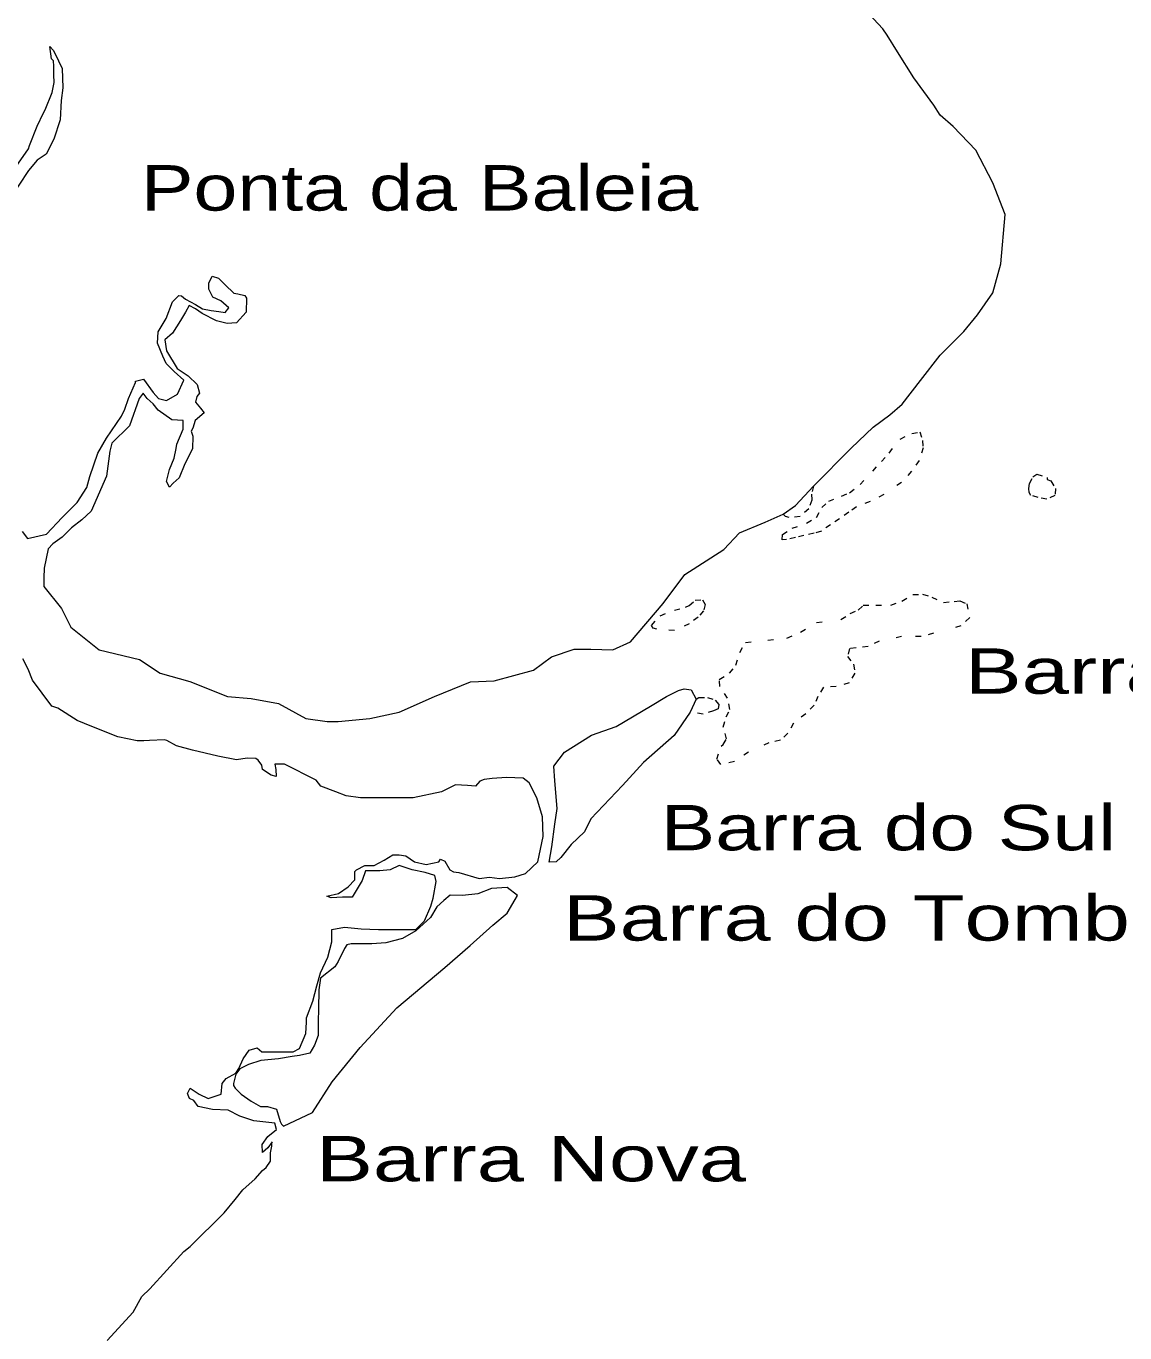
# Model space of a CAD drawing. Extents: x 47169 to 972804, y 7447977 to 9608469.
# Drawn here: x 471352 to 487096, y 8028731 to 8047454 of the extents above; entities that cross this region are included whole.
import ezdxf

# ---------------------------------------------------------------- set-up
doc = ezdxf.new("R2010")
doc.units = 0
doc.header["$LTSCALE"] = 270
doc.linetypes.add('DOTTED', pattern=[1.5, 0.3, -1.2])
doc.layers.add('1', color=7, linetype='Continuous', lineweight=13)
doc.layers.add('3', color=7, linetype='Continuous')

msp = doc.modelspace()

# ---------------------------------------------------------------- linework, layer by layer
at = {"layer": '1'}
for points in [[(475668, 8037489.3), (475821.7, 8037488.3), (476275.4, 8037535.3), (476698.3, 8037626.6), (477205.9, 8037849.5), (477720.9, 8038058.1), (478060.1, 8038072.9), (478620.8, 8038226.2), (478882.5, 8038418.9), (479205.7, 8038526.6), (479444.3, 8038526.9), (479759.2, 8038518.3), (480013.5, 8038633.6), (480482.6, 8039179.5), (480789.7, 8039594.7), (481351.3, 8039955.9), (481574.8, 8040194), (481943.7, 8040348.1), (482198, 8040463.4), (482375, 8040586.4), (482635.6, 8040863.2), (483174.9, 8041409.1), (483489.5, 8041709.2), (483728, 8041885.3), (483904.9, 8042039.2), (484166.6, 8042378), (484451.6, 8042738.8), (484789.6, 8043077.6), (484982.4, 8043315.6), (485205.9, 8043631.1), (485321.2, 8044046.1), (485382.2, 8044753.1), (485205.8, 8045207.7), (484959.4, 8045676.6), (484635.7, 8046014.9), (484451, 8046176.3), (484358.6, 8046323.3), (484074.1, 8046714.8), (483836.2, 8047084.1), (483689.6, 8047322.9), (483628, 8047415.8), (483289.4, 8047777.3)], [(471209.1, 8045441.4), (471385.9, 8045695), (471401.7, 8045741.5), (471508.4, 8046018.2), (471601.5, 8046209.7), (471623.7, 8046256.2), (471724.1, 8046502), (471754.7, 8046648), (471747.1, 8046756.5), (471746.9, 8046879.3), (471746.8, 8046955.6), (471716, 8046986.5), (471692.4, 8047163.5), (471746.6, 8047102.8), (471815.8, 8046955.7), (471870, 8046848.5), (471877.8, 8046571.9), (471854.8, 8046387.1), (471839.2, 8046110.5), (471747.3, 8045833.8), (471639.5, 8045617.9), (471509.1, 8045533.6), (471386.3, 8045387.4), (471109, 8044964.4)], [(473234, 8042910.6), (473242.2, 8043072.2), (473357.6, 8043264.8), (473449.5, 8043502.8), (473541.7, 8043595.9), (473579.9, 8043588.2), (473634, 8043541.8), (473780.5, 8043464.5), (473880.2, 8043402.7), (474003.3, 8043379.6), (474111.5, 8043364.3), (474203.7, 8043348.9), (474256.7, 8043418.7), (474142, 8043518.1), (474026.4, 8043572.2), (473972.1, 8043687.1), (473972, 8043772.3), (474018.5, 8043872), (474110.8, 8043841.1), (474203.2, 8043749.4), (474326.4, 8043625.6), (474387.9, 8043618), (474487.6, 8043594.9), (474511, 8043557.3), (474503.8, 8043357), (474365.1, 8043203.1), (474234.7, 8043195.2), (474079.8, 8043233.7), (473872.9, 8043334.1), (473780.5, 8043402.6), (473688.2, 8043448.9), (473634.2, 8043357), (473564.4, 8043234.1), (473449.1, 8043056.9), (473342.1, 8042957.2), (473364.6, 8042803.5), (473518.7, 8042549.2), (473672.6, 8042442.1), (473804.2, 8042318.4), (473835.1, 8042195.6), (473796, 8042149.1), (473781.2, 8042065), (473850.3, 8041979.9), (473904.4, 8041911.4), (473773.1, 8041803.9), (473742.5, 8041695.4), (473719.2, 8041650), (473742.6, 8041580.3), (473735.5, 8041395.6), (473627.6, 8041180.8), (473543, 8040980.4), (473458.3, 8040904), (473404.3, 8040849.7), (473366, 8040927.1), (473405, 8041103), (473473.7, 8041264.7), (473504.3, 8041403), (473511.6, 8041465), (473604.7, 8041680.8), (473604.5, 8041803.6), (473442.2, 8041811.2), (473242.7, 8041949.2), (473173.6, 8042042), (473088.7, 8042118.3), (473027.1, 8042195.6), (472973.1, 8042119.2), (472834.8, 8041726.3), (472580.6, 8041480.3), (472550, 8041365.2), (472504.9, 8041003.4), (472281.9, 8040504.1), (472150.5, 8040380), (472004.4, 8040264.7), (471866.7, 8040134), (471735.4, 8040034.2), (471666.6, 8039965.5), (471612.9, 8039687.8), (471605.7, 8039549.5), (471605.8, 8039426.7), (471859.7, 8039111.7), (471990.5, 8038841.9), (472398.1, 8038519.4), (472975, 8038380.8), (473275.3, 8038181), (473698.5, 8038065.4), (474237.4, 8037850.3), (474575.6, 8037819.8), (474967.9, 8037750.6), (475360.5, 8037535.3), (475668, 8037489.3)], [(471297.2, 8040211.7), (471373.7, 8040111.2), (471643, 8040172.4), (471866.3, 8040411.7), (472081.3, 8040626.6), (472219.9, 8040841.4), (472266.3, 8041003), (472381.4, 8041334), (472504.1, 8041549.9), (472719, 8041864.4), (472765.5, 8041965.1), (472819.4, 8042119), (472918.7, 8042349.3), (472918.7, 8042364.8), (473034.2, 8042395.9), (473173.4, 8042203.6), (473249.9, 8042118.5), (473365.5, 8042087.7), (473519.2, 8042179.7), (473611.1, 8042380.1), (473473.1, 8042503.8), (473357.4, 8042618.7), (473311.7, 8042726), (473234, 8042910.6)], [(477306, 8036481.1), (476899, 8036396.5), (476606.4, 8036396.2), (476445.3, 8036396), (476145.3, 8036396.8), (475937.5, 8036427.5), (475791.1, 8036481.5), (475575.8, 8036565.3), (475506.8, 8036650.4), (475052.8, 8036881.1), (474913.9, 8036880.9), (474929.9, 8036804.6), (474937.4, 8036703.9), (474861.1, 8036719.3), (474738, 8036804.4), (474729.5, 8036866.3), (474676.4, 8036934.8), (474645.6, 8036958), (474521.5, 8036965.6), (474367.9, 8036943.3), (474098.5, 8036996), (473738, 8037080.8), (473506.8, 8037142.4), (473367.8, 8037219.7), (473337, 8037227.4), (473121.8, 8037219.3), (473037, 8037211.5), (472944.8, 8037211.4), (472668, 8037272.9), (472291.4, 8037419.6), (472083.5, 8037504.5), (471806.6, 8037681.1), (471721.7, 8037712), (471444.5, 8038081.1), (471382.8, 8038242.5), (471306.2, 8038388.5)], [(474871, 8031405.5), (474870.9, 8031452), (474878.3, 8031466.3), (474817, 8031382.2), (474740.8, 8031313.5), (474732.1, 8031428.5), (474816.8, 8031543.7), (474939.6, 8031643.4), (474917.2, 8031736.3), (474617.2, 8031766.9), (474416.8, 8031836.4), (474248.2, 8031920.2), (474024.6, 8031928.8), (473816.8, 8031973.9), (473755.2, 8032059), (473693.7, 8032089.9), (473662.8, 8032158.5), (473702, 8032236), (473832.4, 8032150.9), (473962.9, 8032090.3), (474148.3, 8032151.3), (474162.9, 8032305.2), (474216.9, 8032373.8), (474355.6, 8032451.4), (474401.1, 8032520.1), (474462.4, 8032658.5), (474547, 8032782.5), (474662.5, 8032812.5), (474731.5, 8032758.4), (474823.7, 8032758.5), (475000.7, 8032758.7), (475177.7, 8032759), (475269.9, 8032805.5), (475361.8, 8033020.3), (475370.1, 8033181.8), (475370, 8033243.8), (475462, 8033481.8), (475515.7, 8033705.3), (475569.6, 8033889), (475677.4, 8034112.7), (475731.2, 8034335.1), (475731, 8034512.1), (475915.4, 8034543.3), (476153.9, 8034520.4), (476399.8, 8034511.8), (476745.4, 8034512.2), (476938.3, 8034512.5), (477061.1, 8034635.4), (477153.1, 8034842.4), (477183.7, 8034958.6), (477230.1, 8035196.5), (477206.7, 8035281.7), (477068.8, 8035326.9), (476884.3, 8035365.4), (476699.8, 8035427.1), (476568.4, 8035366.1), (476422.2, 8035350.5), (476214.4, 8035350.2), (476169, 8035211.9), (476023, 8034973.8), (475884.1, 8034973.7), (475723, 8034965.7), (475661.5, 8034988.9), (475830, 8035027.8), (475968.8, 8035119.8), (476060.8, 8035219.5), (476060.7, 8035343.4), (476084, 8035365.5), (476206.9, 8035427.7), (476338.3, 8035427.8), (476483.5, 8035504.3), (476607.4, 8035580.8), (476699.6, 8035580.9), (476791.9, 8035565.5), (476914.9, 8035481.6), (477083.5, 8035443.1), (477267.9, 8035480.9), (477291.2, 8035519.6), (477352.7, 8035488.7), (477421.8, 8035366), (477475.9, 8035335.1), (477553.3, 8035327.4), (477844.9, 8035242.6), (477991.1, 8035258.2), (478137.4, 8035242.9), (478352.6, 8035265.2), (478506.3, 8035311.9), (478683.1, 8035481.4), (478760.1, 8035842.1), (478752.4, 8036126.4), (478668.4, 8036396.3), (478560, 8036611.9), (478475.1, 8036680.4), (478236.6, 8036689), (478029.9, 8036673.3), (477914.3, 8036657.7), (477852.9, 8036634.4), (477791.5, 8036565.7), (477675.9, 8036573.3), (477506.3, 8036580.9), (477306, 8036481.1)], [(472512.5, 8028620.9), (472888.1, 8029028.6), (473011.8, 8029252.3), (473127.2, 8029359.7), (473610.7, 8029898.1), (473702.8, 8029966.8), (474187.6, 8030452), (474348.4, 8030643.6), (474456.3, 8030782.1), (474633.1, 8030936.1), (474740, 8031059), (474794, 8031097.8), (474855.4, 8031189.7), (474855.2, 8031312.5), (474871, 8031405.5)]]:
    msp.add_lwpolyline(points, dxfattribs=at)
at = {"layer": '1', "linetype": 'DOTTED'}
for points in [[(483482.6, 8041077.4), (483607.7, 8041214.7), (483716.8, 8041337.6), (483874.6, 8041538), (484045.2, 8041618.9), (484159.8, 8041640), (484194.9, 8041518.3), (484205.5, 8041411), (484149.5, 8041228.4), (484037.2, 8041077.9), (483895.2, 8040915.1), (483640.9, 8040744.5), (483446.9, 8040640.4), (483248.7, 8040567.2), (483139.6, 8040487.5), (483007.1, 8040396.6), (482877.8, 8040310.2), (482747.5, 8040218.3), (482643.6, 8040187.2), (482498.4, 8040155), (482376.5, 8040126.1), (482246.1, 8040098.4), (482187.8, 8040092.8), (482189.8, 8040169.1), (482327.6, 8040258.8), (482536.4, 8040332), (482676.3, 8040414), (482752.5, 8040555.7), (482852.1, 8040647.6), (483037.6, 8040718.6), (483152.1, 8040767.4), (483302.5, 8040884.8)], [(485983, 8040957.6), (486033.9, 8040936.7), (486101.9, 8040828.3), (486094.5, 8040730.9), (485977.9, 8040677.7), (485852.8, 8040700.9), (485751, 8040730.7), (485723.4, 8040769.4), (485718, 8040830.2), (485727.5, 8040901), (485779.4, 8040995.1), (485834.5, 8041036.1), (485985.1, 8040987.5)], [(482448.7, 8038772), (482679.7, 8038907.2), (483028.5, 8038952.9), (483161, 8039039.2), (483275.4, 8039088), (483348.5, 8039156.7), (483527.7, 8039159), (483740.8, 8039159.2), (483900.9, 8039215.8), (484056.6, 8039309.9), (484198.7, 8039314.5), (484329.2, 8039271.4), (484496.7, 8039197.4), (484649.4, 8039210.8), (484733.2, 8039220.9), (484830.7, 8039177.8), (484873.3, 8038979.8), (484746.2, 8038860.2), (484176.9, 8038707.1), (483897, 8038706.9), (483575.8, 8038643.5), (483417.9, 8038564.8), (483245.1, 8038547), (483148.7, 8038535.9), (483120.1, 8038421.9), (483207.2, 8038312.4), (483227.4, 8038183), (483145.9, 8038045.7), (482958.3, 8037990.3), (482779.1, 8037982.4), (482698.7, 8037849.5), (482642.6, 8037722.2), (482522.9, 8037602.7), (482350.2, 8037465.3), (482265.5, 8037323.6), (482161.7, 8037221.8), (481994.2, 8037186.2), (481703.9, 8037053.2), (481502.6, 8036915.8), (481306.5, 8036875.8), (481250.2, 8036951), (481311.5, 8037136.9), (481342.3, 8037160.2), (481387.8, 8037241), (481342, 8037411.3), (481385.4, 8037556.3), (481436.2, 8037663.6), (481403.1, 8037822.9), (481292.7, 8037991), (481285.2, 8038092.8), (481430.4, 8038183.6), (481522.5, 8038296.5), (481577.5, 8038479.2), (481662.2, 8038622), (481982.3, 8038654.3), (482254.8, 8038685.5)], [(480855.1, 8038892.2), (480643.1, 8038795.8), (480391.8, 8038813.2), (480337.7, 8038826.5), (480312.2, 8038866.3), (480439.3, 8039006.9), (480642.8, 8039085.6), (480800.8, 8039126.7), (480854.8, 8039154.5), (480940.6, 8039228.7), (481045.6, 8039235.4), (481080.6, 8039166.8), (481058.5, 8039078.3), (480982.2, 8038986.4)]]:
    msp.add_lwpolyline(points, close=True, dxfattribs=at)
for points in [[(482635.6, 8040863.2), (482605, 8040747), (482612.5, 8040660.7), (482567, 8040537.9), (482444.1, 8040426), (482287.2, 8040413.7), (482231, 8040429.1), (482198, 8040463.4)], [(480951.5, 8037810.3), (480990.7, 8037833.6), (481114.8, 8037835.9), (481227.2, 8037797.3), (481276, 8037734.3), (481270.8, 8037673.4), (481201.9, 8037642.4), (481051.4, 8037594.7), (480866.9, 8037626.6)]]:
    msp.add_lwpolyline(points, dxfattribs=at)
at = {"layer": '1'}
for points in [[(478929.5, 8036019.3), (478960, 8036241.7), (478928.9, 8036642.2), (478913.8, 8036850.2), (479067.3, 8037049.5), (479451.9, 8037295.5), (479805.9, 8037418.7), (480298.5, 8037711.2), (480528.5, 8037849.7), (480698, 8037934), (480782.8, 8037957.3), (480882.5, 8037941.9), (480951.5, 8037810.3), (480866.9, 8037626.6), (480636.1, 8037287.8), (480198.6, 8036903.5), (479897.9, 8036572.4), (479444.7, 8036096.2), (479352.6, 8035911.3), (479159.9, 8035727.5), (479013.8, 8035542.5), (478944.9, 8035480.5), (478845.3, 8035472.7), (478883.2, 8035696.2)], [(474993.5, 8031758.6), (475009.4, 8031721), (475040.2, 8031690), (475455.4, 8031889.7), (475738.9, 8032328.2), (476139, 8032819.9), (476661.9, 8033389.2), (477353.4, 8033966.4), (477714.5, 8034281), (478037.5, 8034573.4), (478245.1, 8034742.9), (478360.4, 8034942.2), (478391.1, 8034996.5), (478245.7, 8035111.4), (478022.1, 8035096.7), (477822.9, 8035020.2), (477606.6, 8034996.7), (477429.6, 8035004.2), (477337.5, 8034927.8), (477237.9, 8034834.7), (477145.9, 8034680.9), (476938.4, 8034489.2), (476745.6, 8034381.7), (476507.1, 8034320.5), (476307.9, 8034304.8), (476161.6, 8034304.6), (476007.9, 8034304.5), (475946.4, 8034288.9), (475915.8, 8034235.8), (475822.7, 8034050.9), (475777.2, 8033974.5), (475569.7, 8033812.7), (475546.5, 8033643.4), (475539.5, 8033374.5), (475538.6, 8033189.8), (475538.9, 8032989.5), (475485, 8032851.2), (475416.2, 8032736), (475270, 8032704.9), (475163, 8032689.2), (474970.1, 8032659.1), (474716.8, 8032635.6), (474539.9, 8032574.5), (474412.8, 8032512.6), (474356.9, 8032438.7), (474325.1, 8032305.4), (474324.1, 8032274.4), (474347.4, 8032235.7), (474432.3, 8032151.7), (474578.7, 8032051.2), (474709.2, 8031974), (474808.8, 8031974.1), (474940.3, 8031935.5)]]:
    msp.add_lwpolyline(points, close=True, dxfattribs=at)

# ---------------------------------------------------------------- texts
at = {"layer": '3'}
for s, height, width, p in [('Ponta da Baleia', 651, 1.3, (472994.9, 8044811)), ('Barra Leste', 650.7, 1.4, (484804.1, 8037887.8)), ('Barra do Sul', 650.7, 1.35, (480442.6, 8035644.7)), ('Barra do Tomba', 650.6, 1.4, (479044.7, 8034351)), ('Barra Nova', 650.5, 1.4, (475508.6, 8030901.8))]:
    msp.add_text(s, height=height, dxfattribs=dict(at, width=width)).set_placement(p)

doc.saveas('drawing.dxf')
